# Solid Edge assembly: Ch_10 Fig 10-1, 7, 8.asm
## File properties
Author: Cadcim
Template: Iso Assembly.asm
Last saved by: Cadcim
Revision: 1
Application: Solid Edge
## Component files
Ch_10 Fig 10-5 prt 2.par
Ch_10 Fig 10-5 prt 1.par
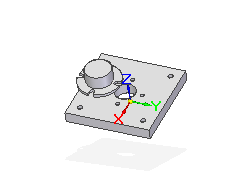
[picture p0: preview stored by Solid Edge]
